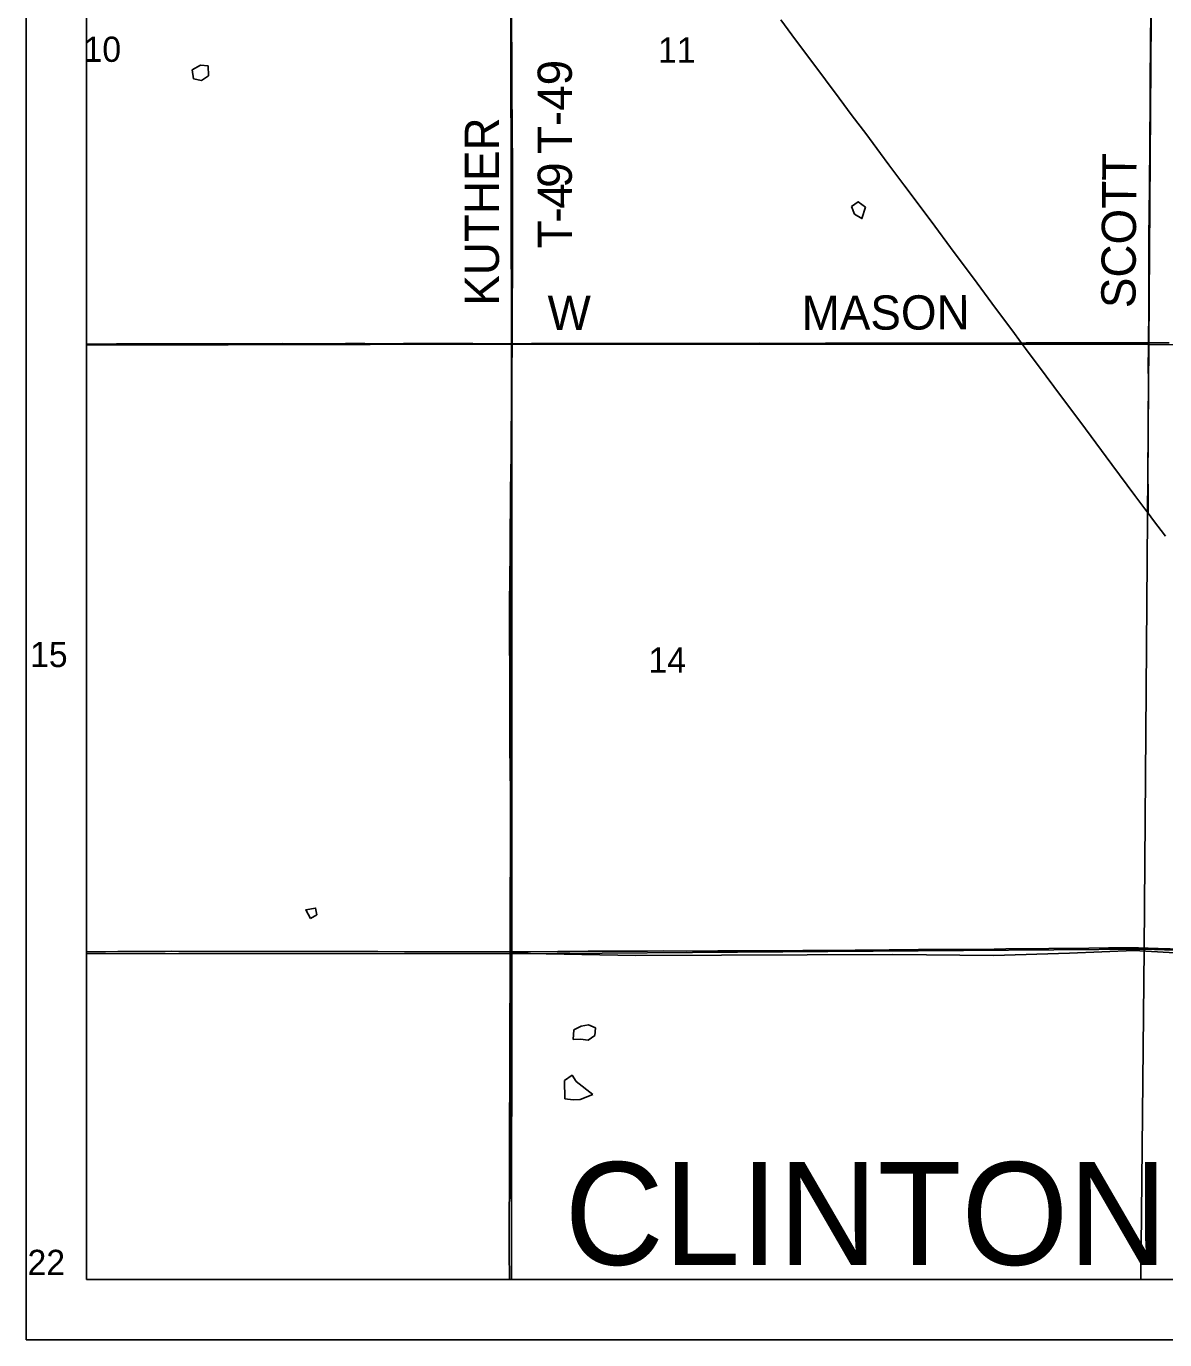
# Model space of a CAD drawing. Extents: x -784 to 1375, y -225 to 440.
# Drawn here: x 442.24 to 480.01, y 281.31 to 324.89 of the extents above; entities that cross this region are included whole.
import ezdxf

# ---------------------------------------------------------------- set-up
doc = ezdxf.new("R2010")
doc.units = 0
for name, color, linetype in [('GM_X_County_Road', 7, 'Continuous'), ('GM_X_County_Road_Text', 7, 'Continuous'), ('GM_X_Minor_Lake', 7, 'Continuous'), ('GM_X_Section', 7, 'Continuous'), ('GM_X_Section_Text', 7, 'Continuous'), ('GM_X_State_Route', 7, 'Continuous'), ('GM_X_Township', 7, 'Continuous'), ('GM_X_Township_Road', 7, 'Continuous'), ('GM_X_Township_Road_Text', 7, 'Continuous'), ('GM_X_Township_Text', 7, 'Continuous'), ('SH_Data', 7, 'Continuous')]:
    doc.layers.add(name, color=color, linetype=linetype)

msp = doc.modelspace()

# ---------------------------------------------------------------- linework, layer by layer
at = {"layer": 'GM_X_County_Road'}
for points in [[(444.236, 314.342), (445.234, 314.346), (449.547, 314.349), (450.752, 314.357), (451.312, 314.352), (451.747, 314.351), (452.02, 314.351), (452.828, 314.357), (453.474, 314.357), (453.81, 314.356), (454.12, 314.354), (454.754, 314.36), (455.76, 314.359), (457.053, 314.357), (457.786, 314.35), (458.36, 314.356)], [(458.36, 314.356), (458.997, 314.36), (460.488, 314.36), (461.283, 314.358), (461.731, 314.364), (462.936, 314.361), (464.663, 314.367), (466.565, 314.369), (467.633, 314.365), (468.752, 314.371), (469.149, 314.371), (469.87, 314.372), (471.088, 314.376), (472.045, 314.376), (473.201, 314.377), (473.909, 314.378), (474.779, 314.375), (475.189, 314.377), (475.254, 314.378)], [(475.254, 314.378), (475.413, 314.38), (476.071, 314.387), (476.978, 314.386), (478.221, 314.383), (479.277, 314.386), (479.474, 314.385)], [(479.474, 314.385), (480.159, 314.384)], [(444.236, 294.18), (444.865, 294.18), (445.275, 294.185), (445.996, 294.192), (446.406, 294.191), (446.605, 294.191), (446.841, 294.194), (447.04, 294.196), (447.3, 294.194), (447.561, 294.191), (447.946, 294.188), (448.096, 294.188), (448.245, 294.19), (448.431, 294.192), (448.505, 294.193), (448.716, 294.195), (448.815, 294.195), (448.902, 294.192), (448.989, 294.194), (449.175, 294.194), (449.523, 294.192), (449.747, 294.193), (449.896, 294.193), (450.356, 294.188), (450.716, 294.189), (451.076, 294.188), (451.498, 294.186), (451.585, 294.186), (451.958, 294.186), (452.095, 294.185), (453.345, 294.191), (453.618, 294.188), (453.904, 294.186), (454.786, 294.184), (455.395, 294.181), (456.141, 294.178), (456.539, 294.176), (457.57, 294.176), (458.179, 294.176), (458.317, 294.175)], [(458.317, 294.175), (458.516, 294.179), (458.963, 294.182), (459.871, 294.187), (460.268, 294.188), (460.877, 294.197), (462.182, 294.203), (462.729, 294.2), (462.846, 294.201)], [(462.846, 294.201), (463.376, 294.207), (464.134, 294.204), (465.178, 294.209), (466.272, 294.213), (467.229, 294.217), (467.999, 294.225), (468.484, 294.223), (468.994, 294.223), (469.74, 294.233), (470.87, 294.245), (471.84, 294.251), (472.312, 294.253), (473.095, 294.258), (473.592, 294.258), (473.965, 294.259), (474.736, 294.273), (476.165, 294.284), (477.495, 294.298), (478.141, 294.309), (478.589, 294.312), (479.135, 294.308), (479.793, 294.292), (480.974, 294.251)]]:
    msp.add_lwpolyline(points, dxfattribs=at)
at = {"layer": 'GM_X_Minor_Lake'}
for p, q in [((447.742, 323.437), (447.782, 323.141)), ((448.278, 323.244), (448.269, 323.57)), ((460.399, 291.593), (460.386, 291.275)), ((461.102, 291.404), (461.122, 291.654))]:
    msp.add_line(p, q, dxfattribs=at)
for points in [[(448.269, 323.57), (448.018, 323.598), (447.742, 323.437)], [(447.782, 323.141), (448.047, 323.09), (448.278, 323.244)], [(470.081, 318.887), (469.834, 319.068), (469.616, 318.912)], [(469.616, 318.912), (469.712, 318.654), (469.961, 318.505), (470.081, 318.887)], [(451.872, 295.403), (451.836, 295.63), (451.506, 295.572), (451.665, 295.286)], [(451.665, 295.286), (451.872, 295.403)], [(461.122, 291.654), (460.895, 291.757), (460.652, 291.717), (460.399, 291.593)], [(460.386, 291.275), (460.629, 291.285), (460.879, 291.249), (461.102, 291.404)], [(461.031, 289.441), (460.484, 289.877), (460.343, 290.085), (460.097, 289.908), (460.105, 289.304)], [(460.105, 289.304), (460.382, 289.273), (460.618, 289.283), (461.031, 289.441)]]:
    msp.add_lwpolyline(points, dxfattribs=at)
at = {"layer": 'GM_X_Section'}
for p, q in [((444.236, 334.405), (444.236, 314.304)), ((444.236, 314.304), (444.236, 294.12)), ((458.332, 283.309), (479.22, 283.309)), ((479.22, 283.309), (499.224, 283.309))]:
    msp.add_line(p, q, dxfattribs=at)
for points in [[(444.236, 314.304), (458.351, 314.341), (458.333, 334.409), (444.236, 334.405)], [(444.236, 294.12), (458.351, 294.115), (458.351, 314.341), (444.236, 314.304)], [(479.22, 283.309), (479.323, 294.268), (458.351, 294.115), (458.332, 283.309)], [(499.224, 283.309), (499.2, 293.85), (490.868, 293.892), (479.323, 294.268), (479.22, 283.309)], [(444.236, 294.12), (444.236, 283.309), (458.332, 283.309)], [(458.332, 283.309), (458.351, 294.115), (444.236, 294.12)]]:
    msp.add_lwpolyline(points, dxfattribs=at)
for points in [[(458.333, 334.409), (479.62, 334.419), (479.486, 314.324), (458.351, 314.341)], [(479.62, 334.419), (499.931, 334.47), (499.901, 324.411), (499.543, 314.191), (479.486, 314.324)], [(479.486, 314.324), (479.323, 294.268), (458.351, 294.115), (458.351, 314.341)], [(499.543, 314.191), (499.2, 293.85), (490.868, 293.892), (479.323, 294.268), (479.486, 314.324)]]:
    msp.add_lwpolyline(points, close=True, dxfattribs=at)
at = {"layer": 'GM_X_State_Route'}
msp.add_lwpolyline([(467.27, 325.102), (467.638, 324.602), (468.757, 323.111), (469.21, 322.503), (469.635, 321.921), (470.086, 321.327), (470.574, 320.668), (470.854, 320.288), (471.356, 319.623), (471.828, 318.998), (472.376, 318.259), (472.9, 317.55), (473.783, 316.364), (474.395, 315.534), (474.931, 314.817), (475.254, 314.378), (475.387, 314.196), (476.072, 313.281), (476.587, 312.594), (477.091, 311.917), (477.384, 311.531), (478.255, 310.351), (479.02, 309.324), (479.353, 308.875), (479.456, 308.736), (479.641, 308.486), (480.034, 307.973)], dxfattribs=at)
at = {"layer": 'GM_X_Township'}
msp.add_line((458.267, 283.309), (539.084, 283.309), dxfattribs=at)
for points in [[(444.236, 382.734), (444.236, 283.309), (458.267, 283.309)], [(458.267, 283.309), (458.263, 284.231), (458.296, 294.134), (458.336, 314.323), (458.289, 334.394), (458.283, 337.182), (458.257, 342.903), (458.257, 344.192), (458.276, 344.705), (458.316, 345.264), (458.426, 346.547), (458.496, 347.13), (458.717, 349.506), (458.868, 351.4), (458.971, 352.658), (459.085, 354.3), (459.121, 359.929), (459.158, 366.091), (446.019, 364.376), (446.293, 382.704), (444.236, 382.734)], [(519.34, 293.604), (517.829, 293.627), (516.502, 293.627), (514.346, 293.626), (507.742, 293.624), (496.837, 293.807), (490.416, 293.843), (485.23, 293.95), (481.696, 294.072), (478.992, 294.22), (476.854, 294.139), (474.329, 294.056), (470.984, 294.092), (462.46, 294.056), (458.296, 294.134), (458.336, 314.323), (458.289, 334.394)], [(539.084, 283.309), (539.15, 292.161), (539.16, 293.586), (533.956, 293.601), (527.265, 293.606), (519.34, 293.604), (517.829, 293.627), (516.502, 293.627), (514.346, 293.626), (507.742, 293.624), (496.837, 293.807), (490.416, 293.843), (485.23, 293.95), (481.696, 294.072), (478.992, 294.22), (476.854, 294.139), (474.329, 294.056), (470.984, 294.092), (462.46, 294.056), (458.296, 294.134), (458.263, 284.231), (458.267, 283.309)]]:
    msp.add_lwpolyline(points, dxfattribs=at)
at = {"layer": 'GM_X_Township_Road'}
for points in [[(479.474, 314.385), (479.477, 315.506), (479.479, 315.953), (479.481, 316.512), (479.486, 317.83), (479.492, 318.762), (479.499, 319.482), (479.51, 321.085), (479.521, 322.365), (479.53, 323.198), (479.538, 324.167), (479.55, 325.509), (479.566, 327.436), (479.573, 327.994), (479.579, 329.051), (479.598, 330.84), (479.615, 333.175)], [(458.36, 314.356), (458.361, 315.183), (458.362, 315.581), (458.37, 316.811), (458.373, 317.719), (458.37, 318.477), (458.372, 318.998), (458.368, 319.483), (458.367, 320.589), (458.362, 321.123), (458.354, 321.794), (458.35, 322.478), (458.346, 322.987), (458.344, 323.534), (458.339, 324.478), (458.336, 325.087)], [(458.317, 294.175), (458.322, 294.363), (458.323, 294.773), (458.325, 295.233), (458.322, 295.941), (458.318, 296.227), (458.317, 296.488), (458.316, 296.898), (458.315, 297.395), (458.316, 298.141), (458.304, 298.924), (458.298, 299.458), (458.288, 300.229), (458.285, 300.962), (458.282, 301.633), (458.279, 302.031), (458.279, 302.541), (458.278, 303.597), (458.274, 304.405), (458.273, 305.66), (458.279, 306.655), (458.286, 307.313), (458.291, 308.109), (458.3, 309.003), (458.3, 309.327), (458.302, 309.575), (458.31, 309.998), (458.321, 310.731), (458.328, 311.402), (458.338, 311.924), (458.344, 312.869), (458.349, 313.689), (458.352, 314.099), (458.36, 314.356)], [(479.456, 308.736), (479.456, 308.994), (479.455, 309.267), (479.451, 310.137), (479.456, 311.007), (479.46, 311.827), (479.466, 313.082), (479.464, 313.642), (479.47, 314.176), (479.474, 314.385)], [(458.334, 283.309), (458.335, 283.91), (458.331, 285.116), (458.33, 285.663), (458.329, 286.297), (458.327, 287.055), (458.326, 287.701), (458.322, 287.925), (458.319, 288.235), (458.315, 288.745), (458.312, 289.105), (458.308, 289.528), (458.308, 290.311), (458.309, 291.666), (458.311, 292.263), (458.311, 293.282), (458.313, 293.854), (458.316, 294.127), (458.317, 294.175)]]:
    msp.add_lwpolyline(points, dxfattribs=at)
at = {"layer": 'SH_Data'}
for p, q in [((442.236, 421.309), (442.236, 281.309)), ((444.236, 419.309), (444.236, 283.309)), ((444.236, 283.309), (580.236, 283.309)), ((442.236, 281.309), (581.184, 281.309))]:
    msp.add_line(p, q, dxfattribs=at)

# ---------------------------------------------------------------- texts
at = {"layer": 'GM_X_County_Road_Text'}
for s, height, rotation, p in [('MASON', 1.1364, 0.1896, (467.964, 314.812)), ('W', 1.136, 0, (459.533, 314.811))]:
    msp.add_text(s, height=height, rotation=rotation, dxfattribs=at).set_placement(p)
at = {"layer": 'GM_X_Section_Text'}
for s, p in [('10', (444.137, 323.707)), ('11', (463.195, 323.682)), ('15', (442.362, 303.626)), ('14', (462.878, 303.439)), ('22', (442.278, 283.455))]:
    msp.add_text(s, height=0.8371, rotation=0, dxfattribs=at).set_placement(p)
at = {"layer": 'GM_X_Township_Road_Text'}
for s, height, rotation, p in [('T-49', 1.1364, 90, (460.339, 320.648)), ('KUTHER', 1.1364, 90, (457.92, 315.615)), ('SCOTT', 1.1364, 89.5644, (479.036, 315.532)), ('9', 1.136, 90.1384, (460.339, 319.529)), ('4', 1.136, 90.1203, (460.34, 318.834)), ('-', 1.136, 90.0954, (460.341, 318.371)), ('T', 1.136, 90.0354, (460.341, 317.521))]:
    msp.add_text(s, height=height, rotation=rotation, dxfattribs=at).set_placement(p)
at = {"layer": 'GM_X_Township_Text'}
msp.add_text('CLINTON', height=3.4091, rotation=0, dxfattribs=at).set_placement((460.094, 283.792))

doc.saveas('drawing.dxf')
